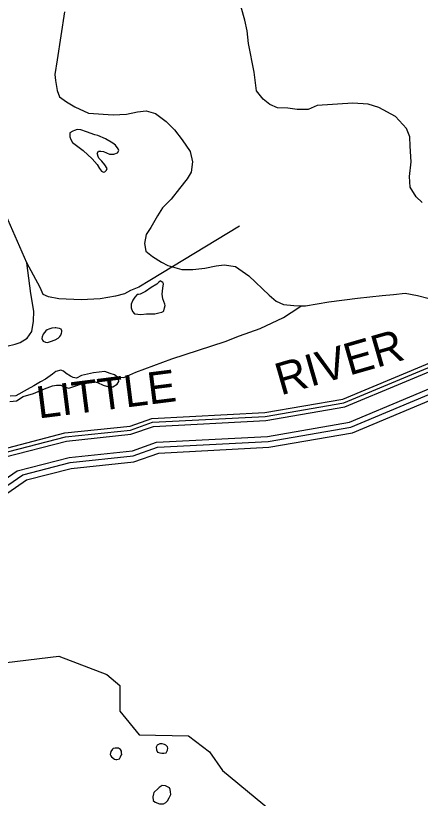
# Model space of a CAD drawing. Extents: x 2260773 to 2342389, y 552869 to 618546.
# Drawn here: x 2288230 to 2290347, y 590931 to 595024 of the extents above; entities that cross this region are included whole.
import ezdxf

# ---------------------------------------------------------------- set-up
doc = ezdxf.new("R2010")
doc.units = 0
for name, color, linetype in [('Exist Hydrographic Buffer Line', 7, 'Continuous'), ('Exist Hydrographic Misc Water Feature', 7, 'Continuous'), ('Exist Hydrographic Pond Under 1500 Sq Ft', 7, 'Continuous'), ('Exist Hydrographic River Shore', 7, 'Continuous'), ('Exist Hydrographic River Shore Label', 7, 'Continuous'), ('Exist Road Non-System Type 51', 7, 'Continuous')]:
    doc.layers.add(name, color=color, linetype=linetype)

msp = doc.modelspace()

# ---------------------------------------------------------------- linework, layer by layer
at = {"layer": 'Exist Hydrographic Buffer Line'}
for points in [[(2288831, 592856.7), (2288946.8, 592897.7), (2289536.1, 592928.3), (2289946.4, 592999.3), (2290532.3, 593242.2)], [(2288842.3, 592748.6), (2288967.6, 592792.9), (2289547.9, 592823), (2289976, 592897.1), (2290607.7, 593161.9), (2290640.6, 593247.6)], [(2288845.2, 592721.3), (2288972.8, 592766.4), (2289550.8, 592796.4), (2289983.5, 592871.3), (2290628.5, 593141.6), (2290665.6, 593238)], [(2288833.4, 592834.3), (2288951.1, 592876), (2289538.5, 592906.5), (2289952.6, 592978.1), (2290555.9, 593228.4)], [(2288146.1, 592732.2), (2288491.5, 592821.1), (2288831, 592856.7)], [(2288170, 592715.1), (2288495.5, 592798.9), (2288833.4, 592834.3)], [(2288238.7, 592643.8), (2288510.8, 592713.8), (2288842.3, 592748.6)], [(2288267.5, 592622.8), (2288515.7, 592686.7), (2288845.2, 592721.3)], [(2287320.3, 591788.9), (2287722.5, 592287.5), (2288238.7, 592643.8)], [(2287355.2, 591778.6), (2287745.6, 592262.6), (2288267.5, 592622.8)]]:
    msp.add_lwpolyline(points, dxfattribs=at)
at = {"layer": 'Exist Hydrographic Misc Water Feature'}
for points in [[(2288486.4, 595042.8), (2288447.1, 594792.5), (2288435.6, 594716.4), (2288438, 594684.8), (2288446.7, 594632.7), (2288459, 594598.9), (2288497.1, 594573.2), (2288539.1, 594547.4), (2288611.5, 594514.3), (2288739.7, 594505.5), (2288809.8, 594508.3), (2288867.2, 594520.7), (2288913.4, 594525.1), (2288961.3, 594511.5), (2289017.7, 594470.1), (2289061.8, 594426.6), (2289100.4, 594374.9), (2289142.8, 594313.4), (2289155.5, 594259.5), (2289148.3, 594205.5), (2289126.6, 594169.4), (2289087.2, 594119), (2289043.8, 594064.7), (2288998, 594018), (2288972.4, 593976.1), (2288937.4, 593915.7), (2288913.4, 593879.5), (2288903.7, 593831.5), (2288911.9, 593791.4), (2288946.4, 593763.8), (2288992.5, 593734.2), (2289026.5, 593716.5), (2289099.1, 593695.4), (2289156.6, 593696.1), (2289220.5, 593702.7), (2289278.4, 593715.1), (2289320.6, 593721.3), (2289380.7, 593711.8), (2289449, 593662.6), (2289555.8, 593561.8), (2289592.3, 593529.9), (2289630.6, 593512.4), (2289684.6, 593507.1), (2289724.1, 593505.6)], [(2290357.1, 594047), (2290324.5, 594076.6), (2290294.2, 594126.6), (2290289.5, 594182.4), (2290299.1, 594258.4), (2290294.2, 594340.3), (2290291.7, 594390.1), (2290275.3, 594433.9), (2290217.1, 594495.5), (2290130.1, 594542.6), (2290074.4, 594559.9), (2289994.4, 594565.1), (2289806.4, 594553.6), (2289760.4, 594533), (2289703, 594532.3), (2289654.6, 594540.1), (2289600.5, 594541.7), (2289560.3, 594559.1), (2289524.6, 594586.8), (2289489.8, 594630.5), (2289477.3, 594728.1), (2289447.7, 594877.8), (2289441.2, 594944), (2289428.9, 594999.8), (2289410, 595067.6)], [(2288644.3, 594400.6), (2288600.2, 594416.2), (2288570.5, 594425.9), (2288552.5, 594427.8), (2288538.1, 594423.5), (2288528.7, 594419.7), (2288514.5, 594411.3), (2288514.5, 594399.5), (2288514.5, 594389.3), (2288518.6, 594375.3), (2288527, 594359.5), (2288583, 594318.2), (2288629.8, 594274.7), (2288655.8, 594244.8), (2288668.3, 594225), (2288680, 594211.2), (2288686.2, 594207.4), (2288692.3, 594205.3), (2288696.4, 594207.1), (2288706.3, 594215.3), (2288708.5, 594223.5), (2288696, 594243.2), (2288681.9, 594263.2), (2288665.9, 594279), (2288661.6, 594286.9), (2288657.7, 594298.9), (2288657.5, 594302.9), (2288663.4, 594315), (2288675.3, 594314.9), (2288689.4, 594313.1), (2288721.4, 594299.4), (2288733.5, 594299.6), (2288743.6, 594299.7), (2288763.3, 594305.6), (2288769.2, 594317.7), (2288767, 594327.8), (2288753, 594345.7), (2288738.9, 594357.6), (2288700.7, 594379.1), (2288660.3, 594397), (2288644.3, 594400.6)], [(2288915.2, 593463.6), (2288957.4, 593464.1), (2288978.8, 593470.2), (2288994.8, 593472.3), (2289001.1, 593476.6), (2289005.2, 593480.5), (2289009.1, 593496.5), (2289012.8, 593508.5), (2289010.8, 593514.5), (2289000.5, 593542.4), (2288996.4, 593566.5), (2288999.7, 593598.5), (2289003.8, 593620.6), (2288999.7, 593628.5), (2288991.7, 593634.2), (2288987.8, 593636.4), (2288979.6, 593630.3), (2288968.1, 593620.3), (2288939.8, 593601.8), (2288910.1, 593581.5), (2288882.4, 593567.5), (2288872.1, 593565.4), (2288866.2, 593565.4), (2288854.5, 593551), (2288842.4, 593535), (2288834.8, 593515), (2288835, 593495.2), (2288841, 593477.2), (2288851.2, 593465.1), (2288869.3, 593463.2), (2288885.1, 593461.6), (2288915.2, 593463.6)], [(2289724.1, 593505.6), (2289746.3, 593505.5), (2289868.1, 593526.9), (2290017.8, 593546.1), (2290147.6, 593559.4), (2290205.6, 593565.7), (2290267.5, 593572.6), (2290331.5, 593560.9), (2290385.8, 593545.4), (2290423.6, 593528), (2290454.1, 593504.3), (2290477.9, 593486.5)], [(2288762.9, 593132.5), (2288766.7, 593132.3), (2288796.5, 593130.7), (2288858.2, 593159.1), (2289047.5, 593229.2), (2289326.5, 593319.7), (2289400.2, 593348.4), (2289509.9, 593387.4), (2289631.2, 593444.6), (2289670.8, 593471), (2289700.6, 593491.3), (2289724.1, 593505.6)], [(2288436.8, 593329.2), (2288453, 593337.3), (2288460.8, 593345.5), (2288466.8, 593353.5), (2288470.4, 593363.5), (2288472.5, 593369.7), (2288472.1, 593375.4), (2288468.4, 593383.7), (2288460.4, 593387.3), (2288448.5, 593389.5), (2288440.3, 593391.2), (2288436.4, 593391.4), (2288420.4, 593389.3), (2288404.4, 593384.8), (2288396, 593380.8), (2288388.2, 593374.7), (2288380.4, 593366.5), (2288374.5, 593358.5), (2288368.7, 593344.8), (2288366.7, 593334.6), (2288370.8, 593326.6), (2288375.1, 593320.7), (2288387.2, 593316.9), (2288397, 593315), (2288413, 593319), (2288436.8, 593329.2)], [(2288762.9, 593132.5), (2288748.1, 593144.5), (2288724.3, 593152.1), (2288696.2, 593162), (2288638.2, 593155.3), (2288574.4, 593142.6), (2288548.8, 593128.3), (2288530.7, 593132.2), (2288516.8, 593138), (2288494.8, 593151.8), (2288480.3, 593163.7), (2288466.3, 593169.5), (2288440.1, 593163.3), (2288422.5, 593149.3), (2288386.8, 593123), (2288360.5, 593108.7), (2288324.9, 593088.6), (2288291.2, 593068.1), (2288232, 593035.7), (2288201.8, 593033.3)], [(2288200, 593005.2), (2288234, 593009.4), (2288269.9, 593032), (2288323.6, 593048.2), (2288381.2, 593072.8), (2288423.3, 593087.2), (2288443.2, 593091.5), (2288467.4, 593091.9), (2288489.3, 593080), (2288509, 593076.2), (2288545.1, 593088.3), (2288568.9, 593096.4), (2288598.8, 593104.9), (2288626.9, 593113.3), (2288658.9, 593105.6), (2288688.8, 593091.8), (2288716.9, 593082.2), (2288739.1, 593082.2), (2288761, 593096.3), (2288770.6, 593110.7), (2288766.7, 593132.3), (2288762.9, 593132.5)], [(2288736.6, 591187.9), (2288728.6, 591175.7), (2288725.1, 591160), (2288728.8, 591153.8), (2288731.3, 591147.8), (2288747.1, 591136), (2288753.6, 591134.2), (2288759.6, 591134.1), (2288773.3, 591138.1), (2288778.8, 591148.3), (2288781.3, 591152.4), (2288785.2, 591160.3), (2288784.8, 591168.5), (2288784.8, 591176.6), (2288778.8, 591186.4), (2288768.8, 591192.4), (2288750.8, 591193.9), (2288741.1, 591192.1), (2288736.6, 591187.9)], [(2289026.3, 591192.5), (2289024.3, 591200.5), (2289016.3, 591208.6), (2289008.5, 591212.3), (2288996.4, 591216.5), (2288984.5, 591216.3), (2288970.8, 591208.2), (2288964.8, 591198.1), (2288966.7, 591184.1), (2288972.8, 591172.2), (2288984.9, 591168.3), (2288994.8, 591166.4), (2289004.6, 591166.6), (2289016.9, 591168.4), (2289024.3, 591182.7), (2289026.3, 591192.5)], [(2288952.7, 590961.9), (2288950.9, 590954.1), (2288947, 590938), (2288949, 590919.9), (2288959.5, 590910.2), (2288983.3, 590902.6), (2289003.2, 590902.8), (2289015.3, 590908.7), (2289025.1, 590916.9), (2289033.3, 590932.7), (2289041.1, 590951), (2289040.7, 590964.9), (2289038.4, 590977), (2289034.8, 590984.8), (2289024.7, 590990.8), (2289014.2, 590996.5), (2288996.2, 590998.3), (2288980.4, 590988.1), (2288974.9, 590982.1), (2288952.7, 590961.9)]]:
    msp.add_lwpolyline(points, dxfattribs=at)
at = {"layer": 'Exist Hydrographic Pond Under 1500 Sq Ft'}
msp.add_lwpolyline([(2288181.7, 591640.6), (2288456.9, 591674.4), (2288707.9, 591577.5), (2288774.7, 591520.4), (2288775.8, 591385.9), (2288876.9, 591262.5), (2289134.8, 591257.3), (2289243.9, 591173.1), (2289311.8, 591076.6), (2289613.8, 590827.8), (2289607.9, 590604.9), (2289558.9, 590478), (2289384.8, 590402.9), (2289085.8, 590356.4), (2288969.7, 590247.2), (2289012.8, 590131.6), (2289088.9, 590031.7), (2289297.8, 589952.1), (2289347.9, 589869), (2289348.9, 589767.4), (2289215.8, 589734)], dxfattribs=at)
at = {"layer": 'Exist Hydrographic River Shore'}
for points in [[(2288828.9, 592877), (2288942.9, 592917.3), (2289533.8, 592948), (2289940.9, 593018.5), (2290513.8, 593256.1)], [(2288848.5, 592690.2), (2288978.8, 592736.3), (2289554.2, 592766.2), (2289992.1, 592842), (2290652.2, 593118.6), (2290693.7, 593226.4)], [(2288121.9, 592747), (2288487.9, 592841.3), (2288828.9, 592877)], [(2288286.4, 592595.5), (2288521.3, 592655.9), (2288848.5, 592690.2)], [(2287383.5, 591760.7), (2287768.5, 592238), (2288286.4, 592595.5)]]:
    msp.add_lwpolyline(points, dxfattribs=at)
at = {"layer": 'Exist Road Non-System Type 51'}
for points in [[(2288288.7, 593730.5), (2288103.2, 594149.9), (2287862.7, 594679.6), (2287612.6, 595215.1), (2287573.2, 595296.5)], [(2289400.4, 593922.9), (2288931.4, 593638.7), (2288873.8, 593604.1), (2288831.8, 593585.8), (2288800.1, 593569.6), (2288752.2, 593557), (2288672.4, 593542.4), (2288572.5, 593537.4), (2288456.5, 593542.4), (2288402.5, 593553.9), (2288374.4, 593565.5), (2288358.1, 593601.4), (2288288.7, 593730.5)], [(2288139.2, 593285.5), (2288227, 593306.3), (2288254.7, 593314.6), (2288290.5, 593336.8), (2288314.2, 593371.2), (2288323.7, 593425.1), (2288325.2, 593479.1), (2288310.3, 593571), (2288288.7, 593730.5)]]:
    msp.add_lwpolyline(points, dxfattribs=at)

# ---------------------------------------------------------------- texts
at = {"layer": 'Exist Hydrographic River Shore Label'}
for s, rotation, p in [('RIVER', 16.0569, (2289616.8, 593037.3)), ('LITTLE', 7.1974, (2288349.8, 592916.5))]:
    msp.add_text(s, height=167.32, rotation=rotation, dxfattribs=at).set_placement(p)

doc.saveas('drawing.dxf')
